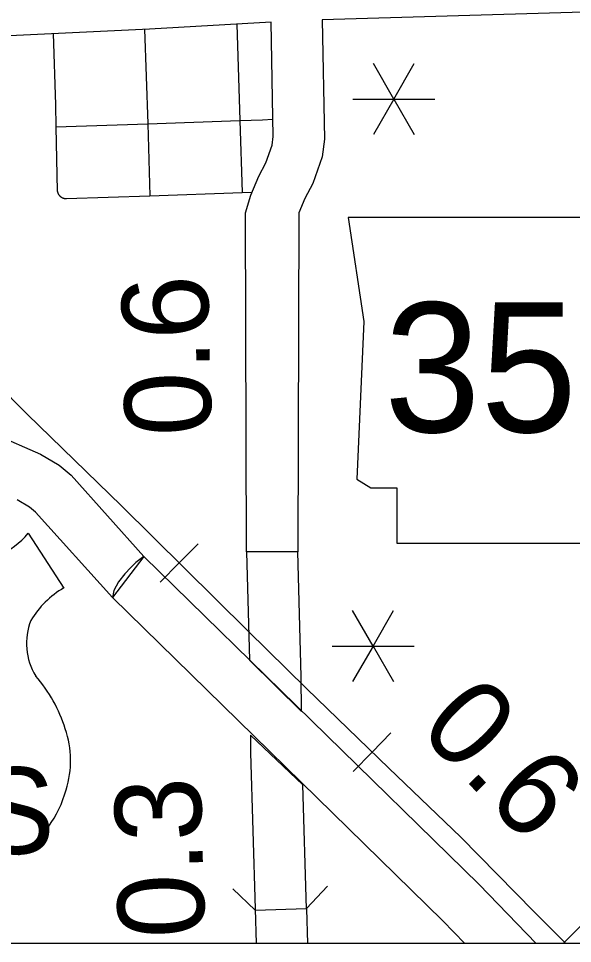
# Model space of a CAD drawing. Extents: x 309348 to 309445, y 336383 to 336484.
# Drawn here: x 309364.558 to 309365.787, y 336384.924 to 336386.977 of the extents above; entities that cross this region are included whole.
import ezdxf

# ---------------------------------------------------------------- set-up
doc = ezdxf.new("R2010")
doc.units = 0
doc.layers.add('R_Annotation', color=7, linetype='Continuous')
doc.layers.add('R_Border Notes', color=7, linetype='Continuous')

msp = doc.modelspace()

# ---------------------------------------------------------------- linework, layer by layer
at = {"layer": 'R_Annotation'}
for p, q in [((309365.3908, 336386.7982), (309365.3454, 336386.8769)), ((309365.3908, 336386.7982), (309365.4363, 336386.8769)), ((309365.2999, 336386.7982), (309365.3908, 336386.7982)), ((309365.3908, 336386.7982), (309365.3454, 336386.7194)), ((309365.3908, 336386.7982), (309365.4818, 336386.7982)), ((309365.3908, 336386.7982), (309365.4363, 336386.7194)), ((309364.5793, 336385.8344), (309364.658, 336385.7127)), ((309364.914, 336385.7685), (309364.9562, 336385.8111)), ((309365.1777, 336385.793), (309365.064, 336385.793)), ((309364.914, 336385.7685), (309364.8718, 336385.7258)), ((309365.3447, 336385.5837), (309365.2992, 336385.6625)), ((309365.3447, 336385.5837), (309365.3901, 336385.6625)), ((309365.2537, 336385.5837), (309365.3447, 336385.5837)), ((309365.3447, 336385.5837), (309365.2992, 336385.505)), ((309365.3447, 336385.5837), (309365.4356, 336385.5837)), ((309365.3447, 336385.5837), (309365.3901, 336385.505)), ((309365.0703, 336385.5527), (309365.1857, 336385.4387)), ((309365.1886, 336385.2757), (309365.0724, 336385.3864)), ((309365.3427, 336385.3484), (309365.3845, 336385.3915)), ((309365.3427, 336385.3484), (309365.3009, 336385.3053)), ((309365.083, 336384.9978), (309365.1966, 336385.0012)), ((309365.1398, 336384.9995), (309365.1398, 336384.9995)), ((309365.7696, 336384.9266), (309365.8121, 336384.969)), ((309365.7696, 336384.9266), (309365.7666, 336384.9236))]:
    msp.add_line(p, q, dxfattribs=at)
for points in [[(309365.7726, 336384.9236), (309365.7018, 336384.9944), (309365.5394, 336385.1596), (309365.3797, 336385.3125), (309365.1979, 336385.4888), (309365.0657, 336385.6182), (309364.7862, 336385.895), (309364.577, 336386.0988), (309364.4338, 336386.242), (309364.2424, 336386.4334), (309364.146, 336386.5243), (309363.5374, 336387.1261), (309363.3584, 336387.301), (309363.1271, 336387.531), (309362.911, 336387.7375), (309362.5888, 336388.0639), (309362.312, 336388.3393), (309361.9651, 336388.6767), (309361.8067, 336388.8323), (309361.6828, 336388.9562), (309361.6085, 336389.0292), (309361.5575, 336389.0705), (309361.5372, 336389.083)], [(309365.7726, 336384.9236), (309365.7018, 336384.9944), (309365.5394, 336385.1596), (309365.3797, 336385.3125), (309365.1979, 336385.4888), (309365.0657, 336385.6182), (309364.7862, 336385.895), (309364.577, 336386.0988), (309364.4338, 336386.242), (309364.2424, 336386.4334), (309364.146, 336386.5243), (309363.5374, 336387.1261), (309363.3584, 336387.301), (309363.1271, 336387.531), (309362.911, 336387.7375)], [(309367.426, 336387.0395), (309365.2318, 336386.9738), (309365.2368, 336386.7094), (309365.232, 336386.6699), (309365.2113, 336386.6105), (309365.1934, 336386.5775), (309365.1801, 336386.5459), (309365.1777, 336385.793), (309365.064, 336385.793), (309365.0612, 336386.5456), (309365.0731, 336386.5846), (309365.0908, 336386.6268), (309365.107, 336386.6567), (309365.1206, 336386.6958), (309365.123, 336386.7151), (309365.1182, 336386.9689), (309364.8488, 336386.9537), (309363.9009, 336386.9083), (309363.6887, 336386.8936), (309363.6599, 336386.8946), (309362.8743, 336386.8681), (309362.7532, 336386.8635), (309362.7488, 336386.9771)], [(309365.042, 336386.9646), (309365.0493, 336386.7506)], [(309364.6347, 336386.9435), (309364.6396, 336386.7853), (309364.6407, 336386.7366)], [(309364.8376, 336386.9531), (309364.8446, 336386.7436)], [(309364.6407, 336386.7366), (309364.8446, 336386.7436)], [(309364.8446, 336386.7436), (309365.0493, 336386.7506)], [(309364.8446, 336386.7436), (309364.8489, 336386.5836)], [(309365.0493, 336386.7506), (309365.0994, 336386.7523), (309365.1223, 336386.7533)], [(309365.0493, 336386.7506), (309365.0543, 336386.5906)], [(309364.6407, 336386.7366), (309364.6439, 336386.5941), (309364.644, 336386.5934), (309364.6442, 336386.5927), (309364.6443, 336386.592), (309364.6445, 336386.5914), (309364.6447, 336386.5907), (309364.645, 336386.5901), (309364.6452, 336386.5895), (309364.6455, 336386.5888), (309364.6458, 336386.5882), (309364.6461, 336386.5876), (309364.6464, 336386.587), (309364.6468, 336386.5864), (309364.6472, 336386.5859), (309364.6476, 336386.5853), (309364.648, 336386.5848), (309364.6484, 336386.5842), (309364.6489, 336386.5837), (309364.6494, 336386.5832), (309364.6498, 336386.5827), (309364.6504, 336386.5823), (309364.6509, 336386.5818)], [(309364.6509, 336386.5818), (309364.6514, 336386.5814), (309364.652, 336386.581), (309364.6525, 336386.5806), (309364.6531, 336386.5802), (309364.6537, 336386.5799), (309364.6543, 336386.5796), (309364.6549, 336386.5792), (309364.6555, 336386.579), (309364.6561, 336386.5787), (309364.6568, 336386.5784), (309364.6574, 336386.5782), (309364.6581, 336386.578), (309364.6588, 336386.5779), (309364.6594, 336386.5777), (309364.6601, 336386.5776), (309364.6608, 336386.5775), (309364.6614, 336386.5774), (309364.6621, 336386.5773), (309364.6628, 336386.5773), (309364.6635, 336386.5773), (309364.6642, 336386.5773), (309364.8489, 336386.5836)], [(309364.8489, 336386.5836), (309365.0543, 336386.5906)], [(309365.0543, 336386.5906), (309365.0759, 336386.5914)], [(309364.5047, 336386.0545), (309364.6066, 336386.0097), (309364.6478, 336385.9853), (309364.6744, 336385.9633), (309364.8358, 336385.7826), (309364.7665, 336385.6918), (309364.5951, 336385.8813), (309364.5822, 336385.8921), (309364.5545, 336385.9085)], [(309365.064, 336385.793), (309365.0703, 336385.5527)], [(309365.1857, 336385.4387), (309365.185, 336385.5162), (309365.1777, 336385.793)], [(309364.8358, 336385.7826), (309364.8178, 336385.7692), (309364.8068, 336385.7586), (309364.7936, 336385.7444), (309364.78, 336385.7268), (309364.7694, 336385.7073), (309364.7665, 336385.6918)], [(309365.7069, 336384.9236), (309365.5802, 336385.0543), (309364.8358, 336385.7826)], [(309364.7665, 336385.6918), (309365.4996, 336384.9741), (309365.5486, 336384.9236)], [(309365.0724, 336385.3864), (309365.0728, 336385.3466), (309365.0829, 336385.0006)], [(309365.1966, 336385.0006), (309365.1886, 336385.2757)], [(309365.0334, 336385.0446), (309365.083, 336384.9978)], [(309365.1966, 336385.0012), (309365.2434, 336385.0508)], [(309365.0829, 336385.0006), (309365.0852, 336384.9236)], [(309365.1966, 336385.0006), (309365.1989, 336384.9236)]]:
    msp.add_lwpolyline(points, dxfattribs=at)
msp.add_lwpolyline([(309365.2894, 336386.5353), (309365.3241, 336386.3045), (309365.3087, 336385.9545), (309365.3394, 336385.9353), (309365.3971, 336385.9353), (309365.3971, 336385.8122), (309365.8818, 336385.8122), (309365.9049, 336385.8622), (309365.8972, 336385.943), (309365.9087, 336386.0353), (309365.951, 336386.1084), (309365.9779, 336386.1622), (309366.0164, 336386.2199), (309366.0395, 336386.2815), (309366.0587, 336386.3315), (309366.0933, 336386.3738), (309366.101, 336386.4007), (309366.0856, 336386.4199), (309365.9664, 336386.4199), (309365.9933, 336386.4738), (309365.9972, 336386.5084), (309365.9812, 336386.535)], close=True, dxfattribs=at)
for centre, radius, start, end in [((309364.4327, 336385.9577), 0.1915, 220.3299, 319.925), ((309364.7608, 336385.536), 0.2045, 120.0117, 149.2191), ((309364.7158, 336385.59), 0.1402, 158.7892, 211.1895), ((309364.3493, 336385.3026), 0.327, 17.3087, 41.0435), ((309364.4572, 336385.3294), 0.2161, 342.6181, 19.0424), ((309364.422, 336385.3301), 0.25, 302.8688, 344.8926)]:
    msp.add_arc(centre, radius, start, end, dxfattribs=at)
at = {"layer": 'R_Border Notes'}
msp.add_line((309372.2951, 336384.9236), (309354.7401, 336384.9236), dxfattribs=at)

# ---------------------------------------------------------------- texts
at = {"layer": 'R_Annotation'}
for s, rotation, p in [('0.6', 91.5068, (309364.9867, 336386.0524)), ('0.6', 314.1172, (309365.4414, 336385.3971)), ('0.3', 91.6803, (309364.9719, 336384.9382))]:
    msp.add_text(s, height=0.19206, rotation=rotation, dxfattribs=at).set_placement(p)
for s, height, p in [('351', 0.28782, (309365.3693, 336386.0588)), ('BUS', 0.19206, (309364.1099, 336385.1227))]:
    msp.add_text(s, height=height, dxfattribs=at).set_placement(p)

doc.saveas('drawing.dxf')
